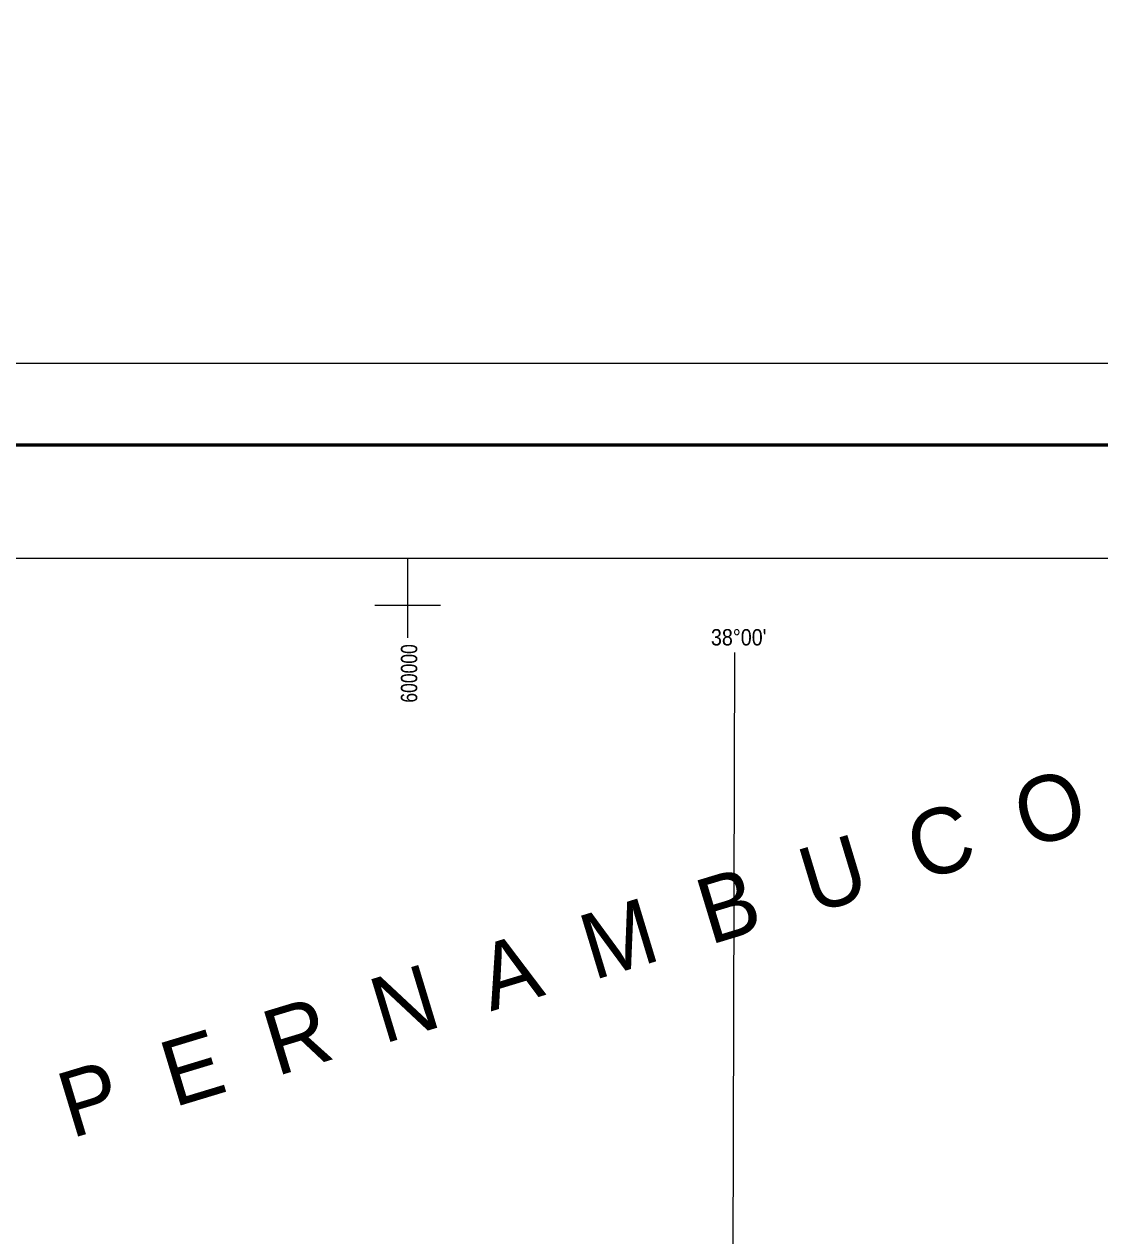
# Model space of a CAD drawing. Extents: x -1643653 to 4543381, y 1624270 to 13878484.
# Drawn here: x 588296 to 621120, y 9005760 to 9042726 of the extents above; entities that cross this region are included whole.
import ezdxf
from ezdxf.enums import TextEntityAlignment as Align

# ---------------------------------------------------------------- set-up
doc = ezdxf.new("R2010")
doc.units = 0
doc.header["$LTSCALE"] = 200
for name, color, linetype, lineweight in [('1', 7, 'Continuous', 13), ('2', 7, 'Continuous', 13), ('3', 7, 'Continuous', 13), ('60', 7, 'Continuous', 13)]:
    doc.layers.add(name, color=color, linetype=linetype, lineweight=lineweight)
for name, color, linetype in [('42', 7, 'Continuous'), ('46', 7, 'Continuous'), ('47', 7, 'Continuous')]:
    doc.layers.add(name, color=color, linetype=linetype)

msp = doc.modelspace()

# ---------------------------------------------------------------- linework, layer by layer
at = {"layer": '1'}
msp.add_lwpolyline([(609971.9, 9023551.8), (609764.7, 8949706.7), (609734.2, 8939404.4)], dxfattribs=at)
at = {"layer": '2'}
for p, q in [((600000, 9024000), (600000, 9026438.8)), ((599000, 9025000), (601000, 9025000))]:
    msp.add_line(p, q, dxfattribs=at)
at = {"layer": '3'}
msp.add_lwpolyline([(842807.3, 9032387.8), (842807.3, 8883887.8), (553961.7, 8883887.8), (553961.7, 9032387.8)], close=True, dxfattribs=at)
msp.add_lwpolyline([(842807.3, 9032387.8), (842807.3, 8883887.8), (553961.7, 8883887.8), (553961.7, 9032387.8)], close=True, dxfattribs=at)
at = {"layer": '3', "lineweight": 53}
msp.add_lwpolyline([(840307.3, 9029887.8), (840307.3, 8886387.8), (560211.7, 8886387.8), (560211.7, 9029887.8)], close=True, dxfattribs=at)
msp.add_lwpolyline([(840307.3, 9029887.8), (840307.3, 8886387.8), (560211.7, 8886387.8), (560211.7, 9029887.8)], close=True, dxfattribs=at)
at = {"layer": '3', "lineweight": 25}
msp.add_lwpolyline([(563033.9, 9026438.8), (793061.1, 9026438.8), (793495.6, 8889836.8), (563468.3, 8889836.8)], close=True, dxfattribs=at)
at = {"layer": '60', "lineweight": 25}
msp.add_spline([(814781, 9009175.5), (814787.2, 9009173.4), (814796.9, 9009173.4), (814799.4, 9009172.4), (814805.1, 9009174.5), (814805.6, 9009176.5), (814811.7, 9009179.5), (814811.7, 9009179.5), (814801.5, 9009181), (814790.7, 9009181.5), (814784.1, 9009183.1), (814777.4, 9009185.1), (814778.4, 9009175.5)], degree=3, dxfattribs=at)

# ---------------------------------------------------------------- texts
at = {"layer": '42'}
msp.add_text('P  E  R  N  A  M  B  U  C  O', height=2000, rotation=16.855, dxfattribs=at).set_placement((589730.9, 9008723.5))
at = {"layer": '46', "width": 0.9}
msp.add_text("38°00'", height=500, dxfattribs=at).set_placement((610099.9, 9023770.4), align=Align.CENTER)
at = {"layer": '47', "width": 0.8}
msp.add_text('600000', height=500, rotation=90, dxfattribs=at).set_placement((600290.6, 9022917.4), align=Align.CENTER)

doc.saveas('drawing.dxf')
